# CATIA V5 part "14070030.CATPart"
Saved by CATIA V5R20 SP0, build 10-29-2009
Part number: 14070030
Definition: NONE
Nomenclature: 14070030
Source: Unknown
Description: 14070030
Bounding box of the stored display mesh (mm): x -15 to 60, y -49 to 39.1, z -39.1 to 39.1
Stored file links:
  C:\Users\Utente\Desktop\IO LAVORO\3D X SITO CF\X SITO\PLASTICA\RF2\14070030.CATPart
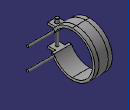
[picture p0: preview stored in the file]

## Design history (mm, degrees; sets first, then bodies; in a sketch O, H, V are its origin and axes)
Body1 "14070030" (main body)
  Solid1: solid without history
